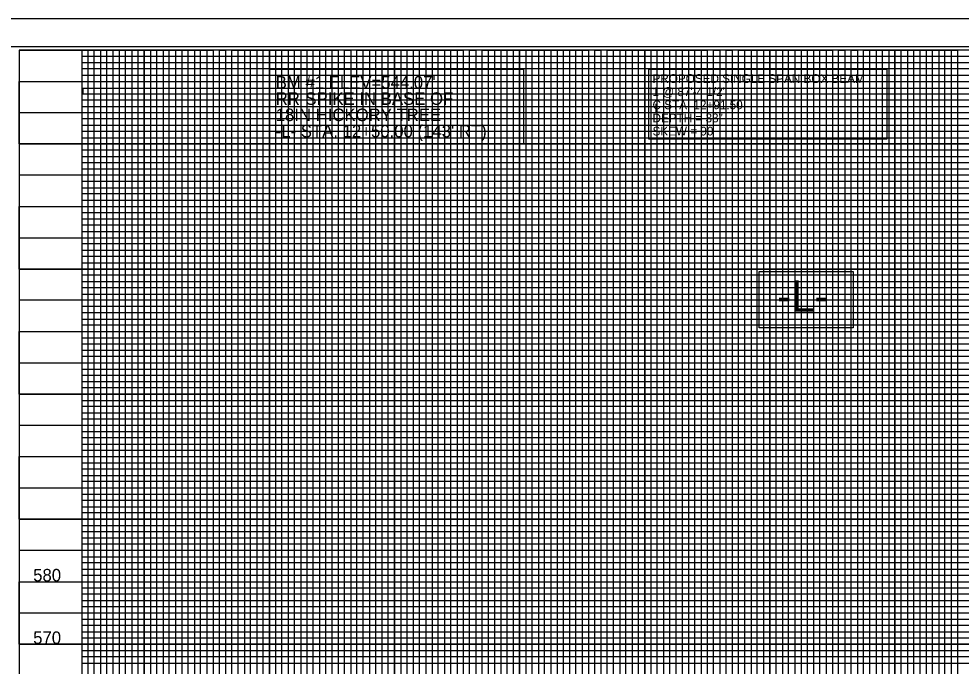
# Model space of a CAD drawing. Extents: x 1735444 to 1737729, y 696688 to 698970.
# Drawn here: x 1736212 to 1736965, y 698218 to 698735 of the extents above; entities that cross this region are included whole.
import ezdxf

# ---------------------------------------------------------------- set-up
doc = ezdxf.new("R2010")
doc.units = 0
for name, color, linetype in [('Exist Vertical Profile Vertical Axis Label', 7, 'Continuous'), ('Old_Level_1', 7, 'Continuous'), ('Prop DSN Text', 7, 'Continuous'), ('Prop Grid Mask', 7, 'Continuous'), ('Prop VPI Label', 7, 'Continuous'), ('Sheet Cutting Line CELL', 7, 'Continuous'), ('Sheet DOT Grid CELL', 7, 'Continuous'), ('Sheet Layout Profile Border', 7, 'Continuous'), ('Sheet Plot Border Inside CELL', 7, 'Continuous'), ('Sheet Plot Border Outside CELL', 7, 'Continuous'), ('Sheet Profile CELL', 7, 'Continuous'), ('Sheet Profile Grid Major CELL', 7, 'Continuous'), ('Sheet Profile Grid Middle CELL', 7, 'Continuous'), ('Sheet Profile Grid Minor CELL', 7, 'Continuous')]:
    doc.layers.add(name, color=color, linetype=linetype)

msp = doc.modelspace()

# ---------------------------------------------------------------- linework, layer by layer
at = {"layer": 'Prop Grid Mask'}
for points in [[(1736412.07, 698694.98), (1736615.12, 698694.98), (1736615.12, 698635.13), (1736412.07, 698635.13)], [(1736715.27, 698694.98), (1736905.56, 698694.98), (1736905.56, 698638.99), (1736715.27, 698638.99)], [(1736803.61, 698533.08), (1736878.61, 698533.08), (1736878.61, 698488.08), (1736803.61, 698488.08)]]:
    msp.add_lwpolyline(points, close=True, dxfattribs=at)
at = {"layer": 'Sheet Cutting Line CELL'}
msp.add_line((1737729.07, 698735.13), (1736045.07, 698735.13), dxfattribs=at)
at = {"layer": 'Sheet DOT Grid CELL'}
for p, q in [((1736262.07, 698710.13), (1736262.07, 697685.13)), ((1736312.07, 698710.13), (1736312.07, 697685.13)), ((1736362.07, 698710.13), (1736362.07, 697685.13)), ((1736412.07, 698710.13), (1736412.07, 697685.13)), ((1736462.07, 698710.13), (1736462.07, 697685.13)), ((1736512.07, 698710.13), (1736512.07, 697685.13)), ((1736562.07, 698710.13), (1736562.07, 697685.13)), ((1736612.07, 698710.13), (1736612.07, 697685.13)), ((1736662.07, 698710.13), (1736662.07, 697685.13)), ((1736712.07, 698710.13), (1736712.07, 697685.13)), ((1736762.07, 698710.13), (1736762.07, 697685.13)), ((1736812.07, 698710.13), (1736812.07, 697685.13)), ((1736862.07, 698710.13), (1736862.07, 697685.13)), ((1736912.07, 698710.13), (1736912.07, 697685.13)), ((1736962.07, 698710.13), (1736962.07, 697685.13)), ((1736212.07, 698685.13), (1737377.62, 698685.13)), ((1736212.07, 698635.13), (1737377.67, 698635.13)), ((1736212.07, 698585.13), (1737512.02, 698585.13)), ((1736212.07, 698535.13), (1737712.07, 698535.13)), ((1736212.07, 698485.13), (1737712.07, 698485.13)), ((1736212.07, 698435.13), (1737712.07, 698435.13)), ((1736212.07, 698385.13), (1737712.07, 698385.13)), ((1736212.07, 698335.13), (1737712.07, 698335.13)), ((1736212.07, 698285.13), (1737712.07, 698285.13)), ((1736212.07, 698235.13), (1737712.07, 698235.13))]:
    msp.add_line(p, q, dxfattribs=at)
at = {"layer": 'Sheet Layout Profile Border'}
msp.add_lwpolyline([(1737512.02, 698661.7), (1737512.02, 698710.13), (1736262.07, 698710.13), (1736262.07, 697685.13), (1737662.07, 697685.13), (1737662.07, 698572.58), (1737512.02, 698572.58), (1737512.02, 698617.69)], dxfattribs=at)
at = {"layer": 'Sheet Plot Border Inside CELL'}
msp.add_lwpolyline([(1737724.57, 698712.68), (1736058.07, 698712.68), (1736058.07, 697657.58), (1737724.57, 697657.58)], close=True, dxfattribs=at)
at = {"layer": 'Sheet Plot Border Outside CELL'}
msp.add_lwpolyline([(1737729.07, 698735.13), (1736045.07, 698735.13), (1736045.07, 697635.13), (1737729.07, 697635.13)], close=True, dxfattribs=at)
at = {"layer": 'Sheet Profile CELL'}
msp.add_lwpolyline([(1737712.07, 698710.13), (1736212.07, 698710.13), (1736212.07, 697660.13), (1737712.07, 697660.13)], close=True, dxfattribs=at)
at = {"layer": 'Sheet Profile Grid Major CELL'}
for points in [[(1736212.07, 698710.13), (1736262.07, 698710.13), (1736262.07, 697685.13)], [(1736312.07, 697685.13), (1736312.07, 698710.13), (1736362.07, 698710.13), (1736362.07, 697685.13)], [(1736412.07, 697685.13), (1736412.07, 698710.13), (1736462.07, 698710.13), (1736462.07, 697685.13)], [(1736512.07, 697685.13), (1736512.07, 698710.13), (1736562.07, 698710.13), (1736562.07, 697685.13)], [(1736612.07, 697685.13), (1736612.07, 698710.13), (1736662.07, 698710.13), (1736662.07, 697685.13)], [(1736712.07, 697685.13), (1736712.07, 698710.13), (1736762.07, 698710.13), (1736762.07, 697685.13)], [(1736812.07, 697685.13), (1736812.07, 698710.13), (1736862.07, 698710.13), (1736862.07, 697685.13)], [(1736912.07, 697685.13), (1736912.07, 698710.13), (1736962.07, 698710.13), (1736962.07, 697685.13)], [(1737377.67, 698635.13), (1736212.17, 698635.13), (1736212.17, 698685.08), (1737377.62, 698685.08)], [(1737712.07, 698535.13), (1736212.07, 698535.13), (1736212.07, 698585.13), (1737512.02, 698585.13)], [(1737712.07, 698435.13), (1736212.07, 698435.13), (1736212.07, 698485.13), (1737712.07, 698485.13)], [(1737712.07, 698335.13), (1736212.07, 698335.13), (1736212.07, 698385.13), (1737712.07, 698385.13)], [(1737712.07, 698235.13), (1736212.07, 698235.13), (1736212.07, 698285.13), (1737712.07, 698285.13)]]:
    msp.add_lwpolyline(points, dxfattribs=at)
at = {"layer": 'Sheet Profile Grid Middle CELL'}
for points in [[(1736287.07, 697685.13), (1736287.07, 698710.13), (1736337.07, 698710.13), (1736337.07, 697685.13)], [(1736387.07, 697685.13), (1736387.07, 698710.13), (1736437.07, 698710.13), (1736437.07, 697685.13)], [(1736487.07, 697685.13), (1736487.07, 698710.13), (1736537.07, 698710.13), (1736537.07, 697685.13)], [(1736587.07, 697685.13), (1736587.07, 698710.13), (1736637.07, 698710.13), (1736637.07, 697685.13)], [(1736687.07, 697685.13), (1736687.07, 698710.13), (1736737.07, 698710.13), (1736737.07, 697685.13)], [(1736787.07, 697685.13), (1736787.07, 698710.13), (1736837.07, 698710.13), (1736837.07, 697685.13)], [(1736887.07, 697685.13), (1736887.07, 698710.13), (1736937.07, 698710.13), (1736937.07, 697685.13)], [(1736212.07, 698660.13), (1737377.67, 698660.13)], [(1737512.02, 698610.13), (1736212.07, 698610.13), (1736212.07, 698560.08), (1737712.07, 698560.08)], [(1737712.07, 698510.13), (1736212.07, 698510.13), (1736212.07, 698460.13), (1737712.07, 698460.13)], [(1737712.07, 698410.13), (1736212.07, 698410.13), (1736212.07, 698360.13), (1737712.07, 698360.13)], [(1737712.07, 698310.13), (1736212.07, 698310.13), (1736212.07, 698260.13), (1737712.07, 698260.13)]]:
    msp.add_lwpolyline(points, dxfattribs=at)
at = {"layer": 'Sheet Profile Grid Minor CELL'}
for p, q in [((1737262.07, 698530.13), (1736262.07, 698530.13)), ((1736262.07, 698530.13), (1736262.07, 698525.13)), ((1736262.07, 698525.13), (1737262.07, 698525.13)), ((1737262.07, 698505.13), (1736262.07, 698505.13))]:
    msp.add_line(p, q, dxfattribs=at)
for points in [[(1736267.07, 698710.13), (1736272.07, 698710.13), (1736277.07, 698710.13), (1736282.07, 698710.13), (1736292.07, 698710.13), (1736259.02, 698710.13), (1736264.02, 698710.13), (1736222.07, 698710.13), (1736227.07, 698710.13), (1736232.07, 698710.13), (1736242.07, 698710.13), (1736247.07, 698710.13), (1736252.07, 698710.13), (1736257.07, 698710.13), (1736267.07, 698710.13), (1736267.07, 697685.13)], [(1736272.07, 697685.13), (1736272.07, 698710.13), (1736277.07, 698710.13), (1736277.07, 697685.13)], [(1736282.07, 697685.13), (1736282.07, 698710.13), (1736292.07, 698710.13), (1736292.07, 697685.13)], [(1736297.07, 697685.13), (1736297.07, 698710.13), (1736302.07, 698710.13), (1736302.07, 697685.13)], [(1736307.07, 697685.13), (1736307.07, 698710.13), (1736317.07, 698710.13), (1736317.07, 697685.13)], [(1736322.07, 697685.13), (1736322.07, 698710.13), (1736327.07, 698710.13), (1736327.07, 697685.13)], [(1736332.07, 697685.13), (1736332.07, 698710.13), (1736342.07, 698710.13), (1736342.07, 697685.13)], [(1736347.07, 697685.13), (1736347.07, 698710.13), (1736352.07, 698710.13), (1736352.07, 697685.13)], [(1736357.07, 697685.13), (1736357.07, 698710.13), (1736367.07, 698710.13), (1736367.07, 697685.13)], [(1736372.07, 697685.13), (1736372.07, 698710.13), (1736377.07, 698710.13), (1736377.07, 697685.13)], [(1736382.07, 697685.13), (1736382.07, 698710.13), (1736392.07, 698710.13), (1736392.07, 697685.13)], [(1736397.07, 697685.13), (1736397.07, 698710.13), (1736402.07, 698710.13), (1736402.07, 697685.13)], [(1736407.07, 697685.13), (1736407.07, 698710.13), (1736417.07, 698710.13), (1736417.07, 697685.13)], [(1736422.07, 697685.13), (1736422.07, 698710.13), (1736427.07, 698710.13), (1736427.07, 697685.13)], [(1736432.07, 697685.13), (1736432.07, 698710.13), (1736442.07, 698710.13), (1736442.07, 697685.13)], [(1736447.07, 697685.13), (1736447.07, 698710.13), (1736452.07, 698710.13), (1736452.07, 697685.13)], [(1736457.07, 697685.13), (1736457.07, 698710.13), (1736467.07, 698710.13), (1736467.07, 697685.13)], [(1736472.07, 697685.13), (1736472.07, 698710.13), (1736472.07, 698710.13), (1736477.07, 698710.13), (1736477.07, 697685.13)], [(1736482.07, 697685.13), (1736482.07, 698710.13), (1736492.07, 698710.13), (1736492.07, 697685.13)], [(1736497.07, 697685.13), (1736497.07, 698710.13), (1736502.07, 698710.13), (1736502.07, 697685.13)], [(1736507.07, 697685.13), (1736507.07, 698710.13), (1736517.07, 698710.13), (1736517.07, 697685.13)], [(1736522.07, 697685.13), (1736522.07, 698710.13), (1736527.07, 698710.13), (1736527.07, 697685.13)], [(1736532.07, 697685.13), (1736532.07, 698710.13), (1736542.07, 698710.13), (1736542.07, 697685.13)], [(1736547.07, 697685.13), (1736547.07, 698710.13), (1736552.07, 698710.13), (1736552.07, 697685.13)], [(1736557.07, 697685.13), (1736557.07, 698710.13), (1736567.07, 698710.13), (1736567.07, 697685.13)], [(1736572.07, 697685.13), (1736572.07, 698710.13), (1736577.07, 698710.13), (1736577.07, 697685.13)], [(1736582.07, 697685.13), (1736582.07, 698710.13), (1736592.07, 698710.13), (1736592.07, 697685.13)], [(1736597.07, 698710.13), (1736597.07, 697685.13), (1736602.07, 697685.13), (1736602.07, 698710.13)], [(1736597.07, 698709.53), (1736597.07, 697685.13), (1736602.07, 697685.13), (1736602.07, 698709.53)], [(1736607.07, 697685.13), (1736607.07, 698710.13), (1736617.07, 698710.13), (1736617.07, 697685.13)], [(1736622.07, 697685.13), (1736622.07, 698710.13), (1736627.07, 698710.13), (1736627.07, 697685.13)], [(1736632.07, 697685.13), (1736632.07, 698710.13), (1736642.07, 698710.13), (1736642.07, 697685.13)], [(1736647.07, 697685.13), (1736647.07, 698710.13), (1736652.07, 698710.13), (1736652.07, 697685.13)], [(1736657.07, 697685.13), (1736657.07, 698710.13), (1736667.07, 698710.13), (1736667.07, 697685.13)], [(1736672.07, 697685.13), (1736672.07, 698710.13), (1736677.07, 698710.13), (1736677.07, 697685.13)], [(1736682.07, 697685.13), (1736682.07, 698710.13), (1736692.07, 698710.13), (1736692.07, 697685.13)], [(1736697.07, 697685.13), (1736697.07, 698710.13), (1736702.07, 698710.13), (1736702.07, 697685.13)], [(1736707.07, 697685.13), (1736707.07, 698710.13), (1736717.07, 698710.13), (1736717.07, 697685.13)], [(1736722.07, 697685.13), (1736722.07, 698710.13), (1736727.07, 698710.13), (1736727.07, 697685.13)], [(1736732.07, 697685.13), (1736732.07, 698710.13), (1736742.07, 698710.13), (1736742.07, 697685.13)], [(1736747.07, 698710.13), (1736747.07, 697685.13), (1736752.07, 697685.13), (1736752.07, 698710.13), (1736757.07, 698710.13), (1736757.07, 697685.13), (1736767.07, 697685.13), (1736767.07, 698710.13), (1736772.07, 698710.13), (1736772.07, 697685.13), (1736777.07, 697685.13), (1736777.07, 698710.13), (1736782.07, 698710.13), (1736782.07, 697685.13)], [(1736792.07, 697685.13), (1736792.07, 698710.13), (1736797.07, 698710.13), (1736797.07, 697685.13)], [(1736802.07, 697685.13), (1736802.07, 698710.13), (1736807.07, 698710.13), (1736807.07, 697685.13)], [(1736817.07, 697685.13), (1736817.07, 698710.13), (1736822.07, 698710.13), (1736822.07, 697685.13)], [(1736827.07, 697685.13), (1736827.07, 698710.13), (1736832.07, 698710.13), (1736832.07, 697685.13)], [(1736842.07, 697685.13), (1736842.07, 698710.13), (1736847.07, 698710.13), (1736847.07, 697685.13)], [(1736852.07, 697685.13), (1736852.07, 698710.13), (1736857.07, 698710.13), (1736857.07, 697685.13)], [(1736867.07, 697685.13), (1736867.07, 698710.13), (1736872.07, 698710.13), (1736872.07, 697685.13)], [(1736877.07, 697685.13), (1736877.07, 698710.13), (1736882.07, 698710.13), (1736882.07, 697685.13)], [(1736892.07, 697685.13), (1736892.07, 698710.13), (1736897.07, 698710.13), (1736897.07, 697685.13)], [(1736902.07, 697685.13), (1736902.07, 698710.13), (1736907.07, 698710.13), (1736907.07, 697685.13)], [(1736917.07, 697685.13), (1736917.07, 698710.13), (1736922.07, 698710.13), (1736922.07, 697685.13)], [(1736927.07, 697685.13), (1736927.07, 698710.13), (1736932.07, 698710.13), (1736932.07, 697685.13)], [(1736942.07, 697685.13), (1736942.07, 698710.13), (1736947.07, 698710.13), (1736947.07, 697685.13)], [(1736952.07, 697685.13), (1736952.07, 698710.13), (1736957.07, 698710.13), (1736957.07, 697685.13)], [(1737262.07, 698705.13), (1736262.07, 698705.13), (1736262.07, 698700.13), (1737262.07, 698700.13)], [(1737262.07, 698695.13), (1736262.07, 698695.13), (1736262.07, 698690.13), (1737262.07, 698690.13)], [(1737262.07, 698679.38), (1736263.07, 698679.38), (1736263.07, 698675.13), (1737262.07, 698675.13)], [(1737262.07, 698670.13), (1736262.07, 698670.13), (1736262.07, 698665.13), (1737262.07, 698665.13)], [(1737262.07, 698655.13), (1736262.07, 698655.13), (1736262.07, 698650.13), (1737262.07, 698650.13)], [(1737262.07, 698645.13), (1736262.07, 698645.13), (1736262.07, 698640.13), (1737262.07, 698640.13)], [(1737262.07, 698630.13), (1736262.07, 698630.13), (1736262.07, 698625.13), (1737262.07, 698625.13)], [(1737262.07, 698620.13), (1736262.07, 698620.13), (1736262.07, 698615.13), (1737262.07, 698615.13)], [(1737262.07, 698605.13), (1736262.07, 698605.13), (1736262.07, 698600.13), (1737262.07, 698600.13)], [(1737262.07, 698595.13), (1736262.07, 698595.13), (1736262.07, 698590.13), (1737262.07, 698590.13)], [(1737262.07, 698580.13), (1736262.07, 698580.13), (1736262.07, 698575.13), (1737262.07, 698575.13)], [(1737262.07, 698570.13), (1736262.07, 698570.13), (1736262.07, 698570.13), (1736262.07, 698550.13), (1737262.07, 698550.13)], [(1736262.07, 698565.13), (1737262.07, 698565.13)], [(1737262.07, 698555.13), (1736262.07, 698555.13)], [(1737262.07, 698545.13), (1736262.07, 698545.13), (1736262.07, 698540.13), (1737262.07, 698540.13)], [(1737262.07, 698520.13), (1736262.07, 698520.13), (1736262.07, 698515.13), (1737262.07, 698515.13)], [(1737262.07, 698500.13), (1736262.07, 698500.13), (1736262.07, 698495.13), (1737262.07, 698495.13)], [(1737262.07, 698490.13), (1736262.07, 698490.13)], [(1736262.07, 698480.13), (1737262.07, 698480.13)], [(1737262.07, 698475.13), (1736262.07, 698475.13), (1736262.07, 698470.13), (1737262.07, 698470.13)], [(1737262.07, 698465.13), (1736262.07, 698465.13), (1736262.07, 698455.13), (1737262.07, 698455.13)], [(1737262.07, 698450.13), (1736262.07, 698450.13), (1736262.07, 698445.13), (1737262.07, 698445.13)], [(1737262.07, 698440.13), (1736262.07, 698440.13), (1736262.07, 698430.13), (1737262.07, 698430.13)], [(1737262.07, 698425.13), (1736262.07, 698425.13), (1736262.07, 698420.13), (1737262.07, 698420.13)], [(1737262.07, 698415.13), (1736262.07, 698415.13), (1736262.07, 698405.13), (1737262.07, 698405.13)], [(1737262.07, 698400.13), (1736262.07, 698400.13), (1736262.07, 698395.13), (1737262.07, 698395.13)], [(1737262.07, 698390.13), (1736262.07, 698390.13), (1736262.07, 698380.13), (1737262.07, 698380.13)], [(1737262.07, 698375.13), (1736262.07, 698375.13), (1736262.07, 698370.13), (1737262.07, 698370.13)], [(1737262.07, 698365.13), (1736262.07, 698365.13), (1736262.07, 698355.13), (1737262.07, 698355.13)], [(1737262.07, 698350.13), (1736262.07, 698350.13), (1736262.07, 698345.13), (1737262.07, 698345.13)], [(1737262.07, 698340.13), (1736262.07, 698340.13), (1736262.07, 698330.13), (1737262.07, 698330.13)], [(1737262.07, 698325.13), (1736262.07, 698325.13), (1736262.07, 698320.13), (1737262.07, 698320.13)], [(1737262.07, 698315.13), (1736262.07, 698315.13), (1736262.07, 698305.13), (1737262.07, 698305.13)], [(1737262.07, 698300.13), (1736262.07, 698300.13), (1736262.07, 698295.13), (1737262.07, 698295.13)], [(1737262.07, 698290.13), (1736262.07, 698290.13), (1736262.07, 698280.13), (1737262.07, 698280.13)], [(1737262.07, 698275.13), (1736262.07, 698275.13), (1736262.07, 698270.13), (1737262.07, 698270.13)], [(1737262.07, 698265.13), (1736262.07, 698265.13), (1736262.07, 698255.13), (1737262.07, 698255.13)], [(1737262.07, 698250.13), (1736262.07, 698250.13), (1736262.07, 698245.13), (1737262.07, 698245.13)], [(1737262.07, 698240.13), (1736262.07, 698240.13), (1736262.07, 698230.13), (1737262.07, 698230.13)], [(1737262.07, 698225.13), (1736262.07, 698225.13), (1736262.07, 698220.13), (1737262.07, 698220.13)]]:
    msp.add_lwpolyline(points, dxfattribs=at)

# ---------------------------------------------------------------- texts
at = {"layer": 'Exist Vertical Profile Vertical Axis Label'}
for s, p in [('580', (1736223.25, 698285.38)), ('570', (1736223.25, 698235.38))]:
    msp.add_text(s, height=10, dxfattribs=at).set_placement(p)
at = {"layer": 'Old_Level_1'}
for s, p in [("BM #1 ELEV=544.07'", (1736417.1, 698679.38)), ('RR-SPIKE IN BASE OF', (1736417.1, 698666.38)), ('18IN HICKORY TREE', (1736417.1, 698653.38)), ("-L- STA. 12+50.00 (143' RT)", (1736417.1, 698640.38))]:
    msp.add_text(s, height=10, dxfattribs=at).set_placement(p)
at = {"layer": 'Prop DSN Text'}
msp.add_text('-L-', height=25, dxfattribs=at).set_placement((1736818.03, 698501.05))
at = {"layer": 'Prop VPI Label'}
for s, p in [('PROPOSED SINGLE SPAN BOX BEAM', (1736718.31, 698683.88)), ('1 @ 87\'-4 1/2"', (1736718.31, 698673.38)), ('C STA. 12+91.50', (1736718.31, 698662.88)), ('L', (1736719.67, 698660.23)), ('DEPTH = 33" ', (1736718.31, 698652.38)), ('SKEW = 90', (1736718.31, 698641.88))]:
    msp.add_text(s, height=7, dxfattribs=at).set_placement(p)

doc.saveas('drawing.dxf')
